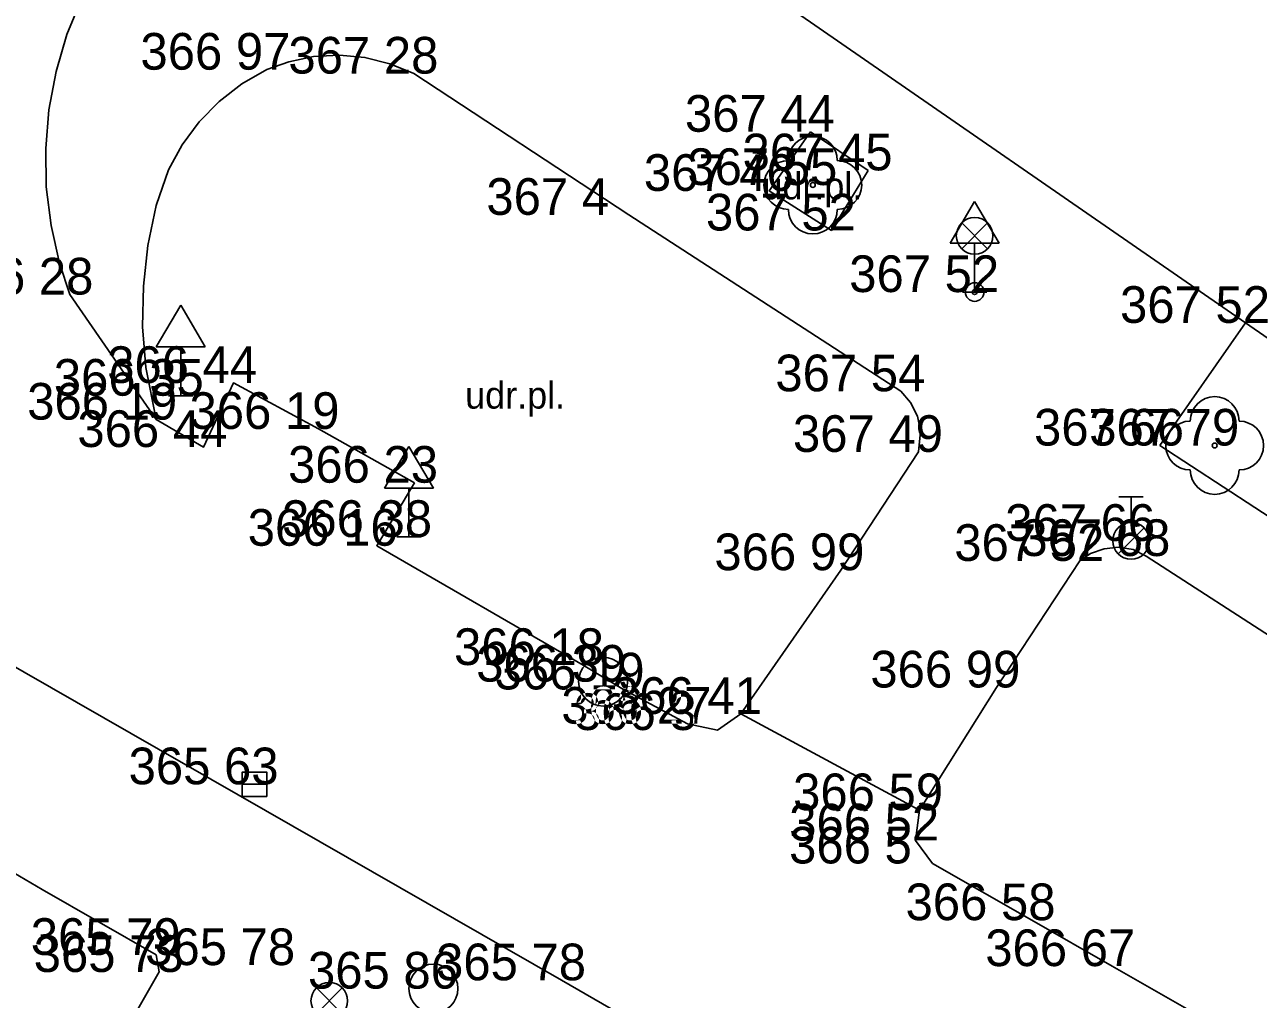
# Model space of a CAD drawing. Extents: x -688316 to -688024, y -973785 to -973591.
# Drawn here: x -688175.42 to -688150.19, y -973674.55 to -973654.61 of the extents above; entities that cross this region are included whole.
import ezdxf

# ---------------------------------------------------------------- set-up
doc = ezdxf.new("R2010")
doc.units = 0
for name, color, linetype in [('Vrstva 10', 7, 'Continuous'), ('Vrstva 22', 7, 'Continuous'), ('Vrstva 27', 7, 'Continuous'), ('Vrstva 28_Verejne osvetleni', 7, 'Continuous'), ('Vrstva 3', 7, 'Continuous'), ('Vrstva 33', 7, 'Continuous'), ('Vrstva 34', 7, 'Continuous'), ('Vrstva 40', 7, 'Continuous'), ('Vrstva 5', 7, 'Continuous'), ('Vrstva 6', 7, 'Continuous')]:
    doc.layers.add(name, color=color, linetype=linetype)

# ---------------------------------------------------------------- blocks, each defined once
blk = doc.blocks.new('DZ')
at = {"layer": 'Vrstva 34'}
for p, q in [((-5, 10), (0, 18.5)), ((0, 18.5), (5, 10)), ((-5, 10), (5, 10)), ((0, 0), (0, 10)), ((-2.49, 0), (2.49, 0))]:
    blk.add_line(p, q, dxfattribs=at)
blk = doc.blocks.new('STL')
at = {"layer": 'Vrstva 22'}
blk.add_circle((0, 0), 0.5, dxfattribs=at)
for centre, start, end in [((0, 5), 0, 180), ((-5, 0), 90, 270), ((5, 0), 270, 90), ((0, -5), 180, 0)]:
    blk.add_arc(centre, 5, start, end, dxfattribs=at)
blk = doc.blocks.new('LA')
at = {"layer": 'Vrstva 33'}
for p, q in [((-2.65, 14.15), (2.65, 8.85)), ((-2.65, 8.85), (2.65, 14.15)), ((0, 0), (0, 7.75))]:
    blk.add_line(p, q, dxfattribs=at)
for centre, radius in [((0, 11.5), 3.75), ((0, 0), 1.9), ((0, 0), 0.5)]:
    blk.add_circle(centre, radius, dxfattribs=at)
blk = doc.blocks.new('ZKUDR0')
at = {"layer": 'Vrstva 40'}
blk.add_text('udr.pl.', height=5.5, dxfattribs=at).set_placement((-11.71, -3.04))
blk = doc.blocks.new('SAK')
at = {"layer": 'Vrstva 27'}
blk.add_circle((0, 0), 5, dxfattribs=at)
blk = doc.blocks.new('HYP')
at = {"layer": 'Vrstva 28_Verejne osvetleni'}
for p, q in [((-2.5, 8.99), (2.5, 8.99)), ((0, 3.75), (0, 8.99)), ((-2.65, -2.65), (2.65, 2.65))]:
    blk.add_line(p, q, dxfattribs=at)
blk.add_circle((0, 0), 3.75, dxfattribs=at)
blk = doc.blocks.new('LAO')
at = {"layer": 'Vrstva 33'}
for p, q in [((-2.65, 14.16), (2.65, 8.85)), ((-2.65, 8.85), (2.65, 14.16)), ((0, 0), (0, 7.75))]:
    blk.add_line(p, q, dxfattribs=at)
blk.add_circle((0, 11.5), 3.75, dxfattribs=at)
blk = doc.blocks.new('VP')
at = {"layer": 'Vrstva 27'}
blk.add_line((-2.5, 0), (2.5, 0), dxfattribs=at)
blk.add_lwpolyline([(-2.5, -2.5), (2.5, -2.5), (2.5, 2.5), (-2.5, 2.5)], close=True, dxfattribs=at)

msp = doc.modelspace()

# ---------------------------------------------------------------- linework, layer by layer
at = {"layer": 'Vrstva 10'}
for p, q in [((-688165.41, -973650.36), (-688150.45, -973660.71)), ((-688163.06, -973658.5), (-688167.46, -973655.61)), ((-688158.17, -973657.59), (-688159.35, -973656.8)), ((-688157.5, -973662.11), (-688163.06, -973658.5)), ((-688174.5, -973660.13), (-688172.73, -973662.69)), ((-688150.45, -973660.71), (-688152.2, -973663.22)), ((-688150.45, -973660.71), (-688131.07, -973674.15)), ((-688169.41, -973662.88), (-688167.45, -973663.98)), ((-688152.2, -973663.22), (-688142.67, -973669.45)), ((-688164.44, -973674.16), (-688182.11, -973664.03)), ((-688152.48, -973665.48), (-688142.05, -973672.25)), ((-688160.77, -973668.71), (-688157.12, -973670.68)), ((-688154.82, -973672.93), (-688153.18, -973673.87)), ((-688153.18, -973673.87), (-688140.93, -973680.86)), ((-688146.68, -973684.36), (-688164.44, -973674.16))]:
    msp.add_line(p, q, dxfattribs=at)
for points in [[(-688174.26, -973654.08), (-688174.56, -973654.81), (-688174.78, -973655.57), (-688174.93, -973656.35), (-688174.99, -973657.14), (-688174.98, -973657.93), (-688174.88, -973658.72), (-688174.71, -973659.49), (-688174.5, -973660.13)], [(-688167.46, -973655.61), (-688167.95, -973655.41), (-688168.46, -973655.28), (-688168.98, -973655.23), (-688169.51, -973655.26), (-688170.02, -973655.37), (-688170.47, -973655.53), (-688170.98, -973655.82), (-688171.44, -973656.18), (-688171.85, -973656.6), (-688172.2, -973657.07), (-688172.48, -973657.58), (-688172.73, -973658.31), (-688172.9, -973659.13), (-688172.99, -973659.96), (-688173.01, -973660.79)], [(-688159.35, -973656.8), (-688160.19, -973658.01), (-688158.92, -973658.82), (-688158.17, -973657.59)], [(-688173.01, -973660.79), (-688172.94, -973661.62), (-688172.73, -973662.69)], [(-688169.41, -973662.88), (-688171.15, -973661.94), (-688171.76, -973663.25), (-688172.73, -973662.69)], [(-688160.77, -973668.71), (-688158.73, -973665.77), (-688157.14, -973663.35), (-688157.1, -973662.93), (-688157.16, -973662.62), (-688157.3, -973662.34), (-688157.5, -973662.11)], [(-688167.45, -973663.98), (-688168.22, -973665.27), (-688164, -973667.71), (-688163.17, -973668.21), (-688161.86, -973668.91), (-688161.25, -973669.04), (-688160.77, -973668.71)], [(-688157.12, -973670.68), (-688155.54, -973668.17), (-688153.84, -973665.58), (-688153.62, -973665.43), (-688153.34, -973665.33), (-688153.05, -973665.3), (-688152.75, -973665.35), (-688152.48, -973665.48)], [(-688157.12, -973670.68), (-688157.2, -973671.3), (-688156.85, -973671.77), (-688154.82, -973672.93)]]:
    msp.add_lwpolyline(points, dxfattribs=at)
at = {"layer": 'Vrstva 5'}
msp.add_lwpolyline([(-688175.06, -973672.3), (-688172.73, -973673.64), (-688172.67, -973673.99), (-688183.21, -973692.44)], dxfattribs=at)
at = {"layer": 'Vrstva 6'}
msp.add_line((-688176.09, -973671.7), (-688175.06, -973672.3), dxfattribs=at)

# ---------------------------------------------------------------- block references
at = {"layer": 'Vrstva 22', "xscale": 0.1, "yscale": 0.10000000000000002}
for p in [(-688159.3, -973657.89), (-688151.08, -973663.22)]:
    msp.add_blockref('STL', p, dxfattribs=at)
at = {"layer": 'Vrstva 27', "xscale": 0.1, "yscale": 0.10000000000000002}
for name, p in [('SAK', (-688163.59, -973668.05)), ('VP', (-688170.72, -973670.15)), ('SAK', (-688167.06, -973674.33))]:
    msp.add_blockref(name, p, dxfattribs=at)
at = {"layer": 'Vrstva 28_Verejne osvetleni', "xscale": 0.1, "yscale": 0.10000000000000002}
msp.add_blockref('HYP', (-688152.79, -973665.17), dxfattribs=at)
at = {"layer": 'Vrstva 33', "xscale": 0.1, "yscale": 0.10000000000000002}
for name, p in [('LA', (-688155.99, -973660.08)), ('LAO', (-688169.19, -973675.73))]:
    msp.add_blockref(name, p, dxfattribs=at)
at = {"layer": 'Vrstva 34', "xscale": 0.1, "yscale": 0.10000000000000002}
for p in [(-688155.99, -973660.08), (-688155.99, -973660.08), (-688155.99, -973660.08), (-688155.99, -973660.08), (-688172.23, -973662.2), (-688172.23, -973662.2), (-688172.23, -973662.2), (-688172.23, -973662.2), (-688167.56, -973665.09), (-688167.56, -973665.09), (-688167.56, -973665.09), (-688167.56, -973665.09)]:
    msp.add_blockref('DZ', p, dxfattribs=at)
at = {"layer": 'Vrstva 40', "xscale": 0.1, "yscale": 0.10000000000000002}
for p in [(-688159.16, -973657.88), (-688165.24, -973662.16)]:
    msp.add_blockref('ZKUDR0', p, dxfattribs=at)

# ---------------------------------------------------------------- texts
at = {"layer": 'Vrstva 3'}
for s, p in [('366 97 ', (-688173.053, -973655.53)), ('366 97 ', (-688173.053, -973655.53)), ('366 97 ', (-688173.053, -973655.53)), ('366 97 ', (-688173.053, -973655.53)), ('366 97 ', (-688173.053, -973655.53)), ('366 97 ', (-688173.053, -973655.53)), ('366 97 ', (-688173.053, -973655.53)), ('367 28 ', (-688170.026, -973655.61)), ('367 28 ', (-688170.026, -973655.61)), ('367 28 ', (-688170.026, -973655.61)), ('367 28 ', (-688170.026, -973655.61)), ('367 28 ', (-688170.026, -973655.61)), ('367 28 ', (-688170.026, -973655.61)), ('367 28 ', (-688170.026, -973655.61)), ('367 44 ', (-688161.916, -973656.8)), ('367 44 ', (-688161.916, -973656.8)), ('367 44 ', (-688161.916, -973656.8)), ('367 44 ', (-688161.916, -973656.8)), ('367 44 ', (-688161.916, -973656.8)), ('367 44 ', (-688161.916, -973656.8)), ('367 44 ', (-688161.916, -973656.8)), ('367 45 ', (-688160.736, -973657.59)), ('367 45 ', (-688160.736, -973657.59)), ('367 45 ', (-688160.736, -973657.59)), ('367 45 ', (-688160.736, -973657.59)), ('367 45 ', (-688160.736, -973657.59)), ('367 45 ', (-688160.736, -973657.59)), ('367 45 ', (-688160.736, -973657.59)), ('367 55 ', (-688161.866, -973657.89)), ('367 55 ', (-688161.866, -973657.89)), ('367 55 ', (-688161.866, -973657.89)), ('367 55 ', (-688161.866, -973657.89)), ('367 55 ', (-688161.866, -973657.89)), ('367 55 ', (-688161.866, -973657.89)), ('367 55 ', (-688161.866, -973657.89)), ('367 46 ', (-688162.756, -973658.01)), ('367 46 ', (-688162.756, -973658.01)), ('367 46 ', (-688162.756, -973658.01)), ('367 46 ', (-688162.756, -973658.01)), ('367 46 ', (-688162.756, -973658.01)), ('367 46 ', (-688162.756, -973658.01)), ('367 46 ', (-688162.756, -973658.01)), ('367 4  ', (-688165.977, -973658.5)), ('367 4  ', (-688165.977, -973658.5)), ('367 4  ', (-688165.977, -973658.5)), ('367 4  ', (-688165.977, -973658.5)), ('367 4  ', (-688165.977, -973658.5)), ('367 4  ', (-688165.977, -973658.5)), ('367 4  ', (-688165.977, -973658.5)), ('367 52 ', (-688161.486, -973658.82)), ('367 52 ', (-688161.486, -973658.82)), ('367 52 ', (-688161.486, -973658.82)), ('367 52 ', (-688161.486, -973658.82)), ('367 52 ', (-688161.486, -973658.82)), ('367 52 ', (-688161.486, -973658.82)), ('367 52 ', (-688161.486, -973658.82)), ('366 28 ', (-688177.083, -973660.13)), ('366 28 ', (-688177.083, -973660.13)), ('366 28 ', (-688177.083, -973660.13)), ('366 28 ', (-688177.083, -973660.13)), ('366 28 ', (-688177.083, -973660.13)), ('366 28 ', (-688177.083, -973660.13)), ('366 28 ', (-688177.083, -973660.13)), ('367 52 ', (-688158.556, -973660.08)), ('367 52 ', (-688158.556, -973660.08)), ('367 52 ', (-688158.556, -973660.08)), ('367 52 ', (-688158.556, -973660.08)), ('367 52 ', (-688158.556, -973660.08)), ('367 52 ', (-688158.556, -973660.08)), ('367 52 ', (-688158.556, -973660.08)), ('367 52 ', (-688153.016, -973660.71)), ('367 52 ', (-688153.016, -973660.71)), ('367 52 ', (-688153.016, -973660.71)), ('367 52 ', (-688153.016, -973660.71)), ('367 52 ', (-688153.016, -973660.71)), ('367 52 ', (-688153.016, -973660.71)), ('367 52 ', (-688153.016, -973660.71)), ('366 44 ', (-688173.733, -973661.94)), ('366 44 ', (-688173.733, -973661.94)), ('366 44 ', (-688173.733, -973661.94)), ('366 44 ', (-688173.733, -973661.94)), ('366 44 ', (-688173.733, -973661.94)), ('366 44 ', (-688173.733, -973661.94)), ('366 44 ', (-688173.733, -973661.94)), ('366 35 ', (-688174.825, -973662.2)), ('366 35 ', (-688174.825, -973662.2)), ('366 35 ', (-688174.825, -973662.2)), ('366 35 ', (-688174.825, -973662.2)), ('366 35 ', (-688174.825, -973662.2)), ('366 35 ', (-688174.825, -973662.2)), ('366 35 ', (-688174.825, -973662.2)), ('367 54 ', (-688160.066, -973662.11)), ('367 54 ', (-688160.066, -973662.11)), ('367 54 ', (-688160.066, -973662.11)), ('367 54 ', (-688160.066, -973662.11)), ('367 54 ', (-688160.066, -973662.11)), ('367 54 ', (-688160.066, -973662.11)), ('367 54 ', (-688160.066, -973662.11)), ('366 19 ', (-688175.369, -973662.69)), ('366 19 ', (-688175.369, -973662.69)), ('366 19 ', (-688175.369, -973662.69)), ('366 19 ', (-688175.369, -973662.69)), ('366 19 ', (-688175.369, -973662.69)), ('366 19 ', (-688175.369, -973662.69)), ('366 19 ', (-688175.369, -973662.69)), ('366 19 ', (-688172.049, -973662.88)), ('366 19 ', (-688172.049, -973662.88)), ('366 19 ', (-688172.049, -973662.88)), ('366 19 ', (-688172.049, -973662.88)), ('366 19 ', (-688172.049, -973662.88)), ('366 19 ', (-688172.049, -973662.88)), ('366 19 ', (-688172.049, -973662.88)), ('366 44 ', (-688174.343, -973663.25)), ('366 44 ', (-688174.343, -973663.25)), ('366 44 ', (-688174.343, -973663.25)), ('366 44 ', (-688174.343, -973663.25)), ('366 44 ', (-688174.343, -973663.25)), ('366 44 ', (-688174.343, -973663.25)), ('366 44 ', (-688174.343, -973663.25)), ('367 66 ', (-688154.775, -973663.22)), ('367 66 ', (-688154.775, -973663.22)), ('367 66 ', (-688154.775, -973663.22)), ('367 66 ', (-688154.775, -973663.22)), ('367 66 ', (-688154.775, -973663.22)), ('367 66 ', (-688154.775, -973663.22)), ('367 66 ', (-688154.775, -973663.22)), ('367 79 ', (-688153.646, -973663.22)), ('367 79 ', (-688153.646, -973663.22)), ('367 79 ', (-688153.646, -973663.22)), ('367 79 ', (-688153.646, -973663.22)), ('367 79 ', (-688153.646, -973663.22)), ('367 79 ', (-688153.646, -973663.22)), ('367 79 ', (-688153.646, -973663.22)), ('367 49 ', (-688159.706, -973663.35)), ('367 49 ', (-688159.706, -973663.35)), ('367 49 ', (-688159.706, -973663.35)), ('367 49 ', (-688159.706, -973663.35)), ('367 49 ', (-688159.706, -973663.35)), ('367 49 ', (-688159.706, -973663.35)), ('367 49 ', (-688159.706, -973663.35)), ('366 23 ', (-688170.033, -973663.98)), ('366 23 ', (-688170.033, -973663.98)), ('366 23 ', (-688170.033, -973663.98)), ('366 23 ', (-688170.033, -973663.98)), ('366 23 ', (-688170.033, -973663.98)), ('366 23 ', (-688170.033, -973663.98)), ('366 23 ', (-688170.033, -973663.98)), ('366 16 ', (-688170.859, -973665.27)), ('366 16 ', (-688170.859, -973665.27)), ('366 16 ', (-688170.859, -973665.27)), ('366 16 ', (-688170.859, -973665.27)), ('366 16 ', (-688170.859, -973665.27)), ('366 16 ', (-688170.859, -973665.27)), ('366 16 ', (-688170.859, -973665.27)), ('366 38 ', (-688170.155, -973665.09)), ('366 38 ', (-688170.155, -973665.09)), ('366 38 ', (-688170.155, -973665.09)), ('366 38 ', (-688170.155, -973665.09)), ('366 38 ', (-688170.155, -973665.09)), ('366 38 ', (-688170.155, -973665.09)), ('366 38 ', (-688170.155, -973665.09)), ('367 66 ', (-688155.365, -973665.17)), ('367 66 ', (-688155.365, -973665.17)), ('367 66 ', (-688155.365, -973665.17)), ('367 66 ', (-688155.365, -973665.17)), ('367 66 ', (-688155.365, -973665.17)), ('367 66 ', (-688155.365, -973665.17)), ('367 66 ', (-688155.365, -973665.17)), ('367 68 ', (-688155.055, -973665.48)), ('367 68 ', (-688155.055, -973665.48)), ('367 68 ', (-688155.055, -973665.48)), ('367 68 ', (-688155.055, -973665.48)), ('367 68 ', (-688155.055, -973665.48)), ('367 68 ', (-688155.055, -973665.48)), ('367 68 ', (-688155.055, -973665.48)), ('366 99 ', (-688161.313, -973665.77)), ('366 99 ', (-688161.313, -973665.77)), ('366 99 ', (-688161.313, -973665.77)), ('366 99 ', (-688161.313, -973665.77)), ('366 99 ', (-688161.313, -973665.77)), ('366 99 ', (-688161.313, -973665.77)), ('366 99 ', (-688161.313, -973665.77)), ('367 52 ', (-688156.406, -973665.58)), ('367 52 ', (-688156.406, -973665.58)), ('367 52 ', (-688156.406, -973665.58)), ('367 52 ', (-688156.406, -973665.58)), ('367 52 ', (-688156.406, -973665.58)), ('367 52 ', (-688156.406, -973665.58)), ('367 52 ', (-688156.406, -973665.58)), ('366 18 ', (-688166.639, -973667.71)), ('366 18 ', (-688166.639, -973667.71)), ('366 18 ', (-688166.639, -973667.71)), ('366 18 ', (-688166.639, -973667.71)), ('366 18 ', (-688166.639, -973667.71)), ('366 18 ', (-688166.639, -973667.71)), ('366 18 ', (-688166.639, -973667.71)), ('366 39 ', (-688166.185, -973668.05)), ('366 39 ', (-688166.185, -973668.05)), ('366 39 ', (-688166.185, -973668.05)), ('366 39 ', (-688166.185, -973668.05)), ('366 39 ', (-688166.185, -973668.05)), ('366 39 ', (-688166.185, -973668.05)), ('366 39 ', (-688166.185, -973668.05)), ('366 19 ', (-688165.809, -973668.21)), ('366 19 ', (-688165.809, -973668.21)), ('366 19 ', (-688165.809, -973668.21)), ('366 19 ', (-688165.809, -973668.21)), ('366 19 ', (-688165.809, -973668.21)), ('366 19 ', (-688165.809, -973668.21)), ('366 19 ', (-688165.809, -973668.21)), ('366 99 ', (-688158.123, -973668.17)), ('366 99 ', (-688158.123, -973668.17)), ('366 99 ', (-688158.123, -973668.17)), ('366 99 ', (-688158.123, -973668.17)), ('366 99 ', (-688158.123, -973668.17)), ('366 99 ', (-688158.123, -973668.17)), ('366 99 ', (-688158.123, -973668.17)), ('366 41 ', (-688163.409, -973668.71)), ('366 41 ', (-688163.409, -973668.71)), ('366 41 ', (-688163.409, -973668.71)), ('366 41 ', (-688163.409, -973668.71)), ('366 41 ', (-688163.409, -973668.71)), ('366 41 ', (-688163.409, -973668.71)), ('366 41 ', (-688163.409, -973668.71)), ('366 27 ', (-688164.443, -973668.91)), ('366 27 ', (-688164.443, -973668.91)), ('366 27 ', (-688164.443, -973668.91)), ('366 27 ', (-688164.443, -973668.91)), ('366 27 ', (-688164.443, -973668.91)), ('366 27 ', (-688164.443, -973668.91)), ('366 27 ', (-688164.443, -973668.91)), ('366 3  ', (-688164.185, -973669.04)), ('366 3  ', (-688164.185, -973669.04)), ('366 3  ', (-688164.185, -973669.04)), ('366 3  ', (-688164.185, -973669.04)), ('366 3  ', (-688164.185, -973669.04)), ('366 3  ', (-688164.185, -973669.04)), ('366 3  ', (-688164.185, -973669.04)), ('365 63 ', (-688173.295, -973670.15)), ('365 63 ', (-688173.295, -973670.15)), ('365 63 ', (-688173.295, -973670.15)), ('365 63 ', (-688173.295, -973670.15)), ('365 63 ', (-688173.295, -973670.15)), ('365 63 ', (-688173.295, -973670.15)), ('365 63 ', (-688173.295, -973670.15)), ('366 59 ', (-688159.703, -973670.68)), ('366 59 ', (-688159.703, -973670.68)), ('366 59 ', (-688159.703, -973670.68)), ('366 59 ', (-688159.703, -973670.68)), ('366 59 ', (-688159.703, -973670.68)), ('366 59 ', (-688159.703, -973670.68)), ('366 59 ', (-688159.703, -973670.68)), ('366 52 ', (-688159.783, -973671.3)), ('366 52 ', (-688159.783, -973671.3)), ('366 52 ', (-688159.783, -973671.3)), ('366 52 ', (-688159.783, -973671.3)), ('366 52 ', (-688159.783, -973671.3)), ('366 52 ', (-688159.783, -973671.3)), ('366 52 ', (-688159.783, -973671.3)), ('366 5  ', (-688159.785, -973671.77)), ('366 5  ', (-688159.785, -973671.77)), ('366 5  ', (-688159.785, -973671.77)), ('366 5  ', (-688159.785, -973671.77)), ('366 5  ', (-688159.785, -973671.77)), ('366 5  ', (-688159.785, -973671.77)), ('366 5  ', (-688159.785, -973671.77)), ('366 58 ', (-688157.403, -973672.93)), ('366 58 ', (-688157.403, -973672.93)), ('366 58 ', (-688157.403, -973672.93)), ('366 58 ', (-688157.403, -973672.93)), ('366 58 ', (-688157.403, -973672.93)), ('366 58 ', (-688157.403, -973672.93)), ('366 58 ', (-688157.403, -973672.93)), ('365 79 ', (-688175.296, -973673.64)), ('365 79 ', (-688175.296, -973673.64)), ('365 79 ', (-688175.296, -973673.64)), ('365 79 ', (-688175.296, -973673.64)), ('365 79 ', (-688175.296, -973673.64)), ('365 79 ', (-688175.296, -973673.64)), ('365 79 ', (-688175.296, -973673.64)), ('365 78 ', (-688172.956, -973673.85)), ('365 78 ', (-688172.956, -973673.85)), ('365 78 ', (-688172.956, -973673.85)), ('365 78 ', (-688172.956, -973673.85)), ('365 78 ', (-688172.956, -973673.85)), ('365 78 ', (-688172.956, -973673.85)), ('365 78 ', (-688172.956, -973673.85)), ('365 73 ', (-688175.236, -973673.99)), ('365 73 ', (-688175.236, -973673.99)), ('365 73 ', (-688175.236, -973673.99)), ('365 73 ', (-688175.236, -973673.99)), ('365 73 ', (-688175.236, -973673.99)), ('365 73 ', (-688175.236, -973673.99)), ('365 73 ', (-688175.236, -973673.99)), ('366 67 ', (-688155.772, -973673.87)), ('366 67 ', (-688155.772, -973673.87)), ('366 67 ', (-688155.772, -973673.87)), ('366 67 ', (-688155.772, -973673.87)), ('366 67 ', (-688155.772, -973673.87)), ('366 67 ', (-688155.772, -973673.87)), ('366 67 ', (-688155.772, -973673.87)), ('365 86 ', (-688169.626, -973674.33)), ('365 86 ', (-688169.626, -973674.33)), ('365 86 ', (-688169.626, -973674.33)), ('365 86 ', (-688169.626, -973674.33)), ('365 86 ', (-688169.626, -973674.33)), ('365 86 ', (-688169.626, -973674.33)), ('365 86 ', (-688169.626, -973674.33)), ('365 78 ', (-688167.006, -973674.16)), ('365 78 ', (-688167.006, -973674.16)), ('365 78 ', (-688167.006, -973674.16)), ('365 78 ', (-688167.006, -973674.16)), ('365 78 ', (-688167.006, -973674.16)), ('365 78 ', (-688167.006, -973674.16)), ('365 78 ', (-688167.006, -973674.16))]:
    msp.add_text(s, height=0.75, dxfattribs=at).set_placement(p)

doc.saveas('drawing.dxf')
